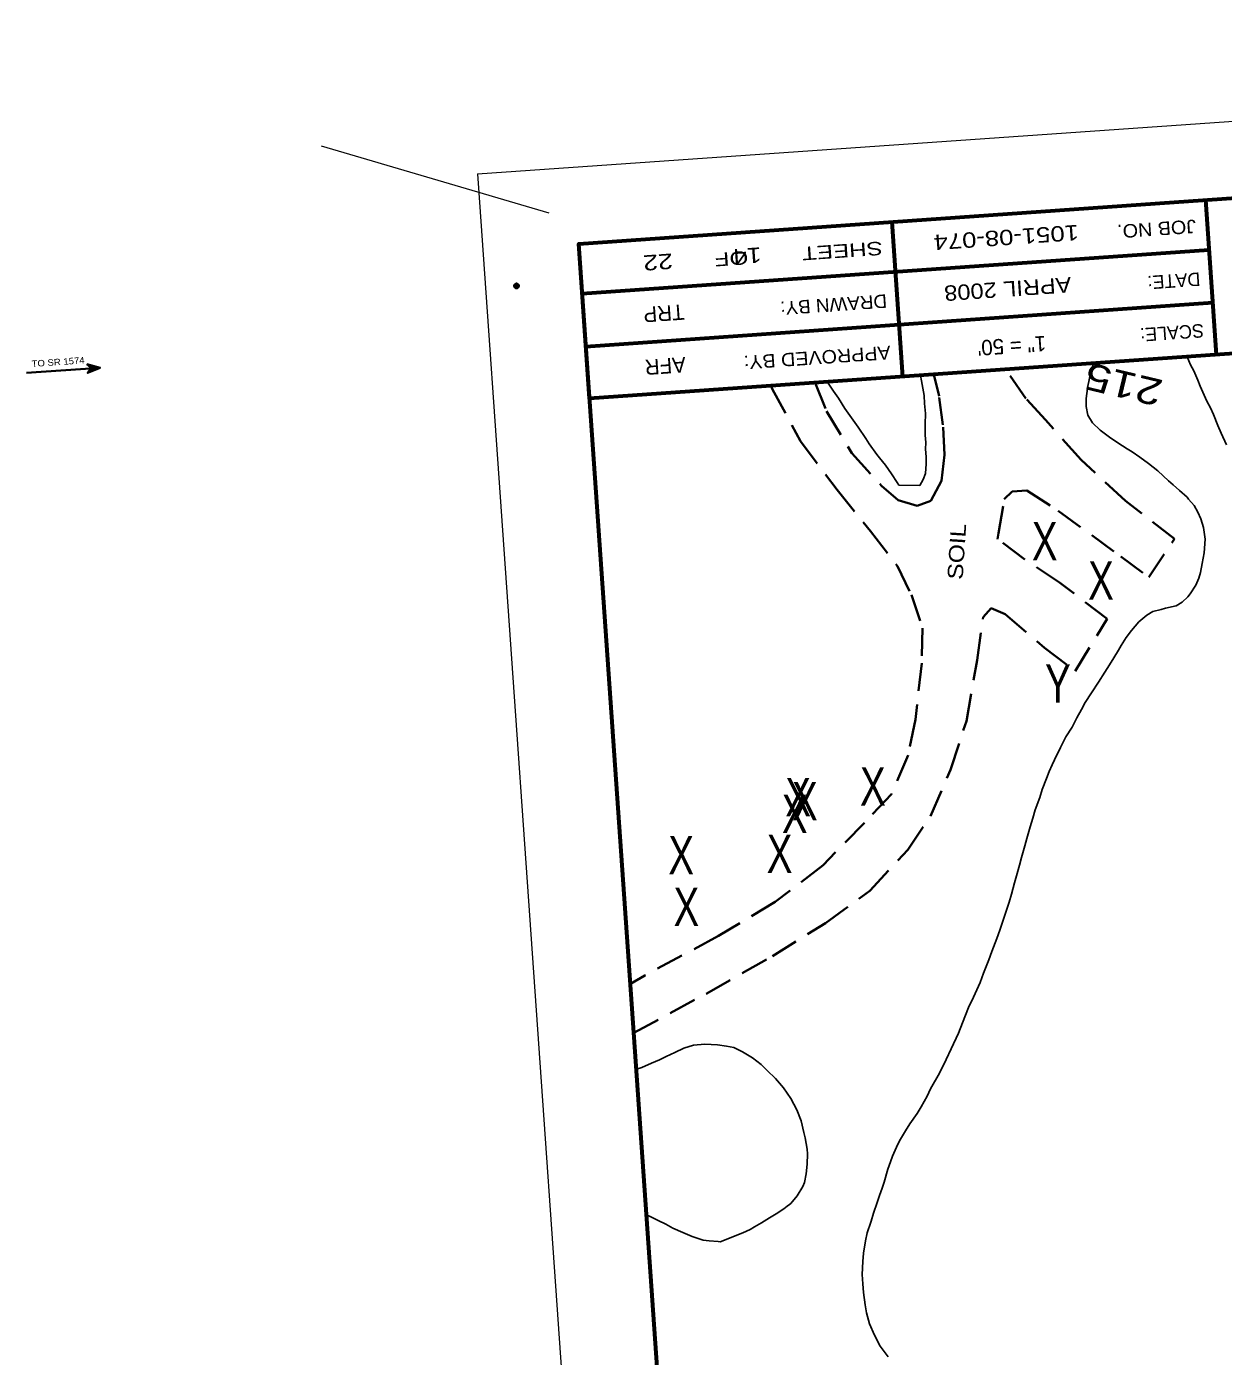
# Model space of a CAD drawing. Extents: x 2399800 to 2400616, y 567347 to 568869.
# Drawn here: x 2399799.6 to 2400111.3, y 568507.5 to 568853.9 of the extents above; entities that cross this region are included whole.
import ezdxf
from ezdxf.enums import TextEntityAlignment as Align

# ---------------------------------------------------------------- set-up
doc = ezdxf.new("R2010")
doc.units = 0
doc.header["$LTSCALE"] = 2.4
doc.header["$PDMODE"] = 32
doc.header["$PDSIZE"] = 1.2
doc.linetypes.add('MEDIUM_DASHED', pattern=[4.5, 3, -1.5])
for name, color, linetype, lineweight in [('10', 7, 'Continuous', 35), ('11', 7, 'Continuous', 25), ('27', 7, 'Continuous', 80), ('3', 7, 'MEDIUM_DASHED', 35), ('61', 7, 'Continuous', 40), ('63', 7, 'Continuous', 35)]:
    doc.layers.add(name, color=color, linetype=linetype, lineweight=lineweight)
doc.layers.add('23', color=7, linetype='Continuous')

msp = doc.modelspace()

# ---------------------------------------------------------------- hatches: boundary and pattern name
at = {"layer": '10'}
msp.add_hatch(color=256, dxfattribs=at).paths.add_polyline_path([(2399815.265, 568765.953), (2399818.71, 568765.066), (2399815.422, 568763.708), (2399816.466, 568764.909)])

# ---------------------------------------------------------------- linework, layer by layer
msp.add_lwpolyline([(2399815.265, 568765.953), (2399818.71, 568765.066), (2399815.422, 568763.708), (2399816.466, 568764.909)], close=True, dxfattribs=at)
at = {"layer": '11'}
for points in [[(2400081.651, 568746.964), (2400079.227, 568748.804), (2400077.188, 568750.67), (2400076.011, 568752.728), (2400075.537, 568754.922), (2400075.587, 568757.047), (2400076.009, 568760.266), (2400076.665, 568763.53), (2400077.383, 568766.101), (2400077.409, 568766.179)], [(2400101.855, 568767.889), (2400102.775, 568765.818), (2400103.562, 568764.269), (2400104.615, 568761.846), (2400105.242, 568760.241), (2400105.954, 568758.701), (2400107.017, 568756.354), (2400107.933, 568754.635), (2400108.691, 568752.861), (2400109.845, 568750.045), (2400110.722, 568748.027), (2400112.146, 568744.947)], [(2400032.444, 568763.035), (2400032.645, 568761.685), (2400032.817, 568760.673), (2400033.352, 568757.786), (2400033.462, 568755.716), (2400033.661, 568753.177), (2400033.598, 568750.368), (2400033.6, 568747.475), (2400033.803, 568745.545), (2400033.737, 568743.878), (2400033.856, 568741.883), (2400033.836, 568739.983), (2400033.737, 568737.483), (2400033.081, 568735.97), (2400032.192, 568734.412), (2400026.799, 568734.509)], [(2400026.799, 568734.509), (2400026.354, 568735.177), (2400024.822, 568737.433), (2400023.291, 568739.689), (2400021.71, 568741.572), (2400021.07, 568742.493), (2400019.073, 568745.267), (2400018.182, 568746.602), (2400016.13, 568749.536), (2400014.394, 568751.971), (2400012.732, 568754.397), (2400011.035, 568757.132), (2400009.753, 568758.975), (2400008.853, 568760.235), (2400008.184, 568761.339)], [(2400019.482, 568542.518), (2400019.561, 568542.757), (2400020.135, 568544.813), (2400021.116, 568547.654), (2400021.736, 568549.476), (2400022.44, 568551.363), (2400022.945, 568552.896), (2400023.921, 568556.27), (2400024.56, 568558.243), (2400025.13, 568559.69), (2400026.118, 568561.997), (2400026.952, 568563.715), (2400028.503, 568566.253), (2400029.581, 568568.091), (2400031.536, 568570.804), (2400032.604, 568572.568), (2400034.11, 568575.34), (2400035.038, 568577.198), (2400037.329, 568581.313), (2400039.092, 568584.889), (2400040.362, 568587.616), (2400042.269, 568591.706), (2400043.316, 568594.461), (2400044.903, 568598.441), (2400046.239, 568601.083), (2400047.956, 568604.893), (2400048.814, 568607.37), (2400050.183, 568610.845), (2400051.001, 568613.022), (2400052.276, 568616.357), (2400053.094, 568618.534), (2400054.487, 568622.767), (2400055.497, 568625.832), (2400056.081, 568627.964), (2400056.848, 568630.909), (2400057.393, 568632.741), (2400058.214, 568635.526), (2400058.704, 568637.518), (2400059.555, 568640.528), (2400060.11, 568642.434), (2400060.961, 568645.444), (2400061.639, 568647.716), (2400062.308, 568649.912), (2400063.488, 568653.108), (2400064.137, 568655.155), (2400065.203, 568658.06), (2400065.897, 568659.873), (2400066.657, 568661.601), (2400067.292, 568662.964), (2400068.846, 568666.11), (2400070.277, 568668.892), (2400071.902, 568671.42), (2400073.134, 568673.847), (2400074.337, 568676.049), (2400075.33, 568677.823), (2400076.956, 568680.351), (2400078.771, 568683.158), (2400080.406, 568685.761), (2400081.644, 568687.655), (2400082.722, 568689.493), (2400083.97, 568691.461), (2400084.661, 568692.665), (2400086.003, 568694.773), (2400087.381, 568696.572), (2400089.276, 568698.836), (2400091.337, 568700.622), (2400092.907, 568701.558), (2400095.111, 568702.106), (2400096.217, 568702.418), (2400098.965, 568703.048), (2400100.534, 568703.985), (2400102.013, 568705.39), (2400102.644, 568706.144), (2400104.156, 568708.383), (2400104.86, 568710.27), (2400105.356, 568711.728), (2400105.809, 568714.028), (2400106.257, 568716.863), (2400106.569, 568720.4), (2400106.127, 568723.427), (2400105.439, 568725.726), (2400104.672, 568727.425), (2400103.68, 568729.154), (2400102.22, 568730.792), (2400101.83, 568731.3), (2400099.855, 568733.081), (2400098.216, 568734.515), (2400096.986, 568735.589), (2400094.212, 568738.237), (2400091.798, 568740.152), (2400089.57, 568741.738), (2400087.546, 568743.146), (2400086.202, 568743.931), (2400083.814, 568745.462), (2400081.651, 568746.964)], [(2399958.407, 568582.339), (2399959.788, 568582.796), (2399962.294, 568583.914), (2399964.388, 568584.782), (2399966.172, 568585.614), (2399968.369, 568586.696), (2399970.726, 568587.834), (2399973.269, 568588.643), (2399976.192, 568588.869), (2399979.515, 568588.662), (2399981.835, 568588.358), (2399983.761, 568587.953), (2399986.058, 568586.89), (2399988.671, 568585.33), (2399990.88, 568583.594), (2399992.425, 568582.021), (2399994.66, 568579.901), (2399996.705, 568577.501), (2399998.627, 568574.736), (2400000.22, 568571.787), (2400001.289, 568568.906), (2400002.029, 568565.84), (2400002.386, 568564.498), (2400002.837, 568561.546), (2400002.979, 568560.309), (2400002.851, 568557.585), (2400002.602, 568555.105), (2400002.148, 568552.804), (2400001.786, 568551.786), (2400000.255, 568549.398), (2399998.623, 568547.404), (2399997.353, 568546.429), (2399997.12, 568546.264)], [(2399980.183, 568537.41), (2399979.659, 568537.479), (2399977.394, 568537.624), (2399975.747, 568537.84), (2399972.896, 568538.746), (2399970.45, 568539.828), (2399967.928, 568540.92), (2399966.09, 568541.998), (2399964.082, 568542.947), (2399962.149, 568543.885), (2399961.061, 568544.391)], [(2399997.12, 568546.264), (2399995.257, 568544.952), (2399993.03, 568543.645), (2399991.027, 568542.309), (2399989.139, 568541.262), (2399988.058, 568540.566), (2399986.114, 568539.679), (2399980.183, 568537.41)], [(2400017.587, 568524.209), (2400017.422, 568526.439), (2400017.212, 568528.903), (2400017.345, 568532.236), (2400017.554, 568534.416), (2400018.051, 568537.625), (2400018.55, 568539.691), (2400019.482, 568542.518)], [(2400023.995, 568507.457), (2400021.923, 568510.241), (2400020.396, 568513.106), (2400019.102, 568516.017), (2400018.332, 568518.858), (2400017.998, 568520.958), (2400017.587, 568524.209)]]:
    msp.add_lwpolyline(points, dxfattribs=at)
at = {"layer": '27', "lineweight": 35}
msp.add_line((2399818.71, 568765.066), (2399799.553, 568763.726), dxfattribs=at)
at = {"layer": '3'}
msp.add_line((2400037.25, 568757.607), (2400035.887, 568763.276), dxfattribs=at)
for points in [[(2400054.226, 568730.801), (2400056.242, 568732.821), (2400060.082, 568733.079), (2400068.3, 568727.814), (2400084.55, 568715.863), (2400091.84, 568710.492), (2400098.558, 568720.499), (2400085.844, 568730.387), (2400074.222, 568741.047), (2400064.93, 568751.478), (2400059.869, 568757.014), (2400054.546, 568764.581)], [(2399993.512, 568760.313), (2399993.805, 568759.57), (2400001.149, 568745.893), (2400010.68, 568733.223), (2400019.399, 568722.487), (2400026.424, 568713.344), (2400030.022, 568705.944), (2400032.911, 568697.191), (2400032.706, 568688.081), (2400031.093, 568673.446), (2400029.183, 568664.103), (2400024.816, 568654.016), (2400017.823, 568646.557), (2400007.008, 568635.488), (2399994.563, 568625.927), (2399979.772, 568617.054), (2399960.609, 568606.775), (2399956.854, 568604.555)], [(2400004.925, 568761.111), (2400007.891, 568753.765), (2400014.52, 568742.77), (2400022.241, 568734.297), (2400026.545, 568730.535), (2400031.527, 568729.045), (2400035.131, 568730.4), (2400037.868, 568735.599), (2400038.676, 568742.345), (2400038.254, 568750.167), (2400037.25, 568757.607)], [(2400052.462, 568720.444), (2400052.749, 568721.924), (2400054.226, 568730.801)], [(2400048.706, 568700.076), (2400050.846, 568702.46), (2400054.442, 568700.847), (2400064.717, 568692.115), (2400072.678, 568686.047), (2400081.008, 568699.65), (2400068.621, 568709.115), (2400059.583, 568715.096), (2400052.462, 568720.444)], [(2399957.747, 568591.782), (2399976.583, 568602.017), (2399993.851, 568611.783), (2400007.621, 568620.41), (2400019.225, 568628.786), (2400029.084, 568639.524), (2400035.025, 568648.262), (2400040.181, 568660.301), (2400044.359, 568673.002), (2400047.121, 568688.856), (2400048.706, 568700.076)]]:
    msp.add_lwpolyline(points, dxfattribs=at)
msp.add_point((2399927.172, 568786.363), dxfattribs=at)
at = {"layer": '63', "lineweight": 13}
for p, q in [((2399917.038, 568815.546), (2400465.699, 568853.912)), ((2399935.688, 568805.343), (2399876.368, 568822.792)), ((2399917.038, 568815.546), (2399976.331, 567967.616))]:
    msp.add_line(p, q, dxfattribs=at)
at = {"layer": '63'}
msp.add_line((2400442.155, 568832.216), (2399943.373, 568797.338), dxfattribs=at)
at = {"layer": '63', "lineweight": 60}
for p, q in [((2400106.636, 568808.755), (2400109.456, 568768.421)), ((2400027.825, 568762.712), (2400025.004, 568803.046)), ((2399999.405, 567996.031), (2399943.373, 568797.338)), ((2400107.548, 568795.711), (2399944.285, 568784.294)), ((2400108.512, 568781.927), (2399945.249, 568770.51))]:
    msp.add_line(p, q, dxfattribs=at)
msp.add_lwpolyline([(2400444.975, 568791.882), (2399946.193, 568757.004), (2399943.373, 568797.338), (2400442.155, 568832.216)], close=True, dxfattribs=at)

# ---------------------------------------------------------------- texts
at = {"layer": '11', "width": 0.75}
for s, p in [('X', (2400064.758, 568714.872)), ('X', (2400079.408, 568704.653)), ('Y', (2400068.199, 568677.799)), ('X', (2400019.994, 568650.998)), ('X', (2400000.52, 568648.22)), ('X', (2400002.283, 568647.152)), ('X', (2399999.642, 568643.843)), ('X', (2399970.063, 568633.101)), ('X', (2399995.694, 568633.473)), ('X', (2399971.416, 568619.6))]:
    msp.add_text(s, height=10, dxfattribs=at).set_placement(p, align=Align.CENTER)
at = {"layer": '23'}
for s, height, rotation, width, p in [('TO SR 1574', 1.688, 4, 1.1, (2399807.812, 568765.715)), ('SOIL', 4, 86.307, 1.2, (2400043.85, 568717.035))]:
    msp.add_text(s, height=height, rotation=rotation, dxfattribs=dict(at, width=width)).set_placement(p, align=Align.CENTER)
at = {"layer": '61', "width": 1.3}
msp.add_text('215', height=7, rotation=166.537, dxfattribs=at).set_placement((2400086.096, 568764.076), align=Align.CENTER)
at = {"layer": '63'}
for s, width, p in [('1051-08-074', 1.25, (2400054.604, 568800.99)), ('14        22', 1.3, (2399975.455, 568795.377)), ('APRIL 2008', 1.15, (2400054.992, 568787.551))]:
    msp.add_text(s, height=4, rotation=184, dxfattribs=dict(at, width=width)).set_placement(p, align=Align.CENTER)
for s, width, p in [('JOB NO.', 1.1, (2400104.064, 568803.677)), ('SHEET        OF', 1.35, (2400022.433, 568797.968)), ('DRAWN BY:', 1.05, (2400023.551, 568784.198)), ('APPROVED BY:', 1.1, (2400024.489, 568770.785))]:
    msp.add_text(s, height=3.5, rotation=184, dxfattribs=dict(at, width=width)).set_placement(p)
for s, p in [('DATE:', (2400105.162, 568789.905)), ('SCALE:', (2400106.1, 568776.492))]:
    msp.add_text(s, height=3.5, rotation=184, dxfattribs=at).set_placement(p)
for s, p in [('TRP', (2399965.437, 568781.21)), ('1" = 50\'', (2400056.026, 568772.767)), ('AFR', (2399965.78, 568767.504))]:
    msp.add_text(s, height=4, rotation=184, dxfattribs=at).set_placement(p, align=Align.CENTER)

doc.saveas('drawing.dxf')
